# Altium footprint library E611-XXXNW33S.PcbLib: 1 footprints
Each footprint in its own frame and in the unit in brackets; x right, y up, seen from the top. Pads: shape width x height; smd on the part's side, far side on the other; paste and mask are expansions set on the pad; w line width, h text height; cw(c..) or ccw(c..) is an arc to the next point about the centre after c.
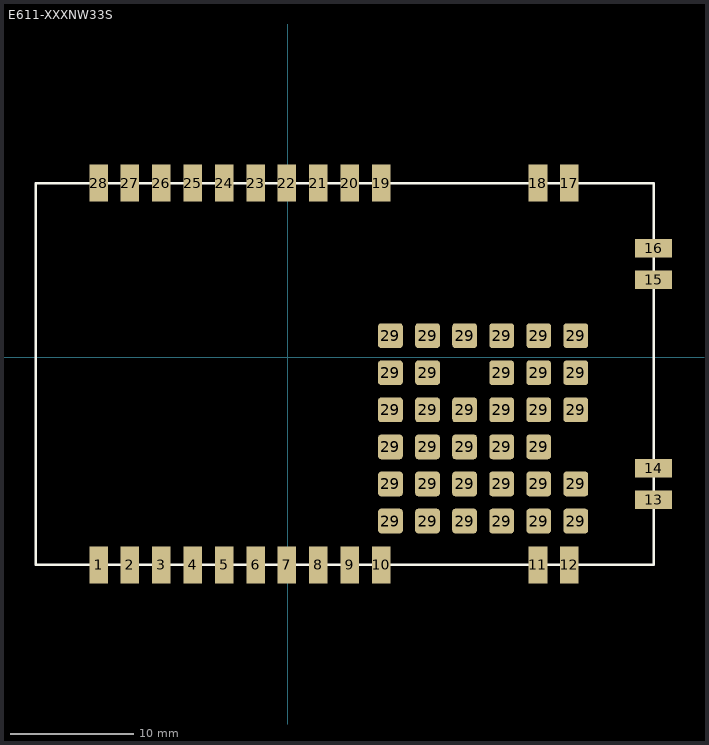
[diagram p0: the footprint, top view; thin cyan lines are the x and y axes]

## E611-XXXNW33S [mm]
pads (62):
  rect 1.5x3 smd: 1(-15.291,-16.815) 2(-12.751,-16.815) 3(-10.211,-16.815) 4(-7.671,-16.815) 5(-5.131,-16.815) 6(-2.591,-16.815) 7(-0.051,-16.815) 8(2.489,-16.815) 9(5.029,-16.815) 10(7.569,-16.815) 11(20.269,-16.815) 12(22.809,-16.815) 17(22.809,14.085) 18(20.269,14.085) 19(7.569,14.085) 20(5.029,14.085) 21(2.489,14.085) 22(-0.051,14.085) 23(-2.591,14.085) 24(-5.131,14.085) 25(-7.671,14.085) 26(-10.211,14.085) 27(-12.751,14.085) 28(-15.291,14.085)
  rect 3x1.5 smd: 13(29.629,-11.525) 14(29.629,-8.985) 15(29.629,6.255) 16(29.629,8.795)
  rrect25% 2x2 smd paste-2 mask-2: 29(8.329,-13.265) 29(8.329,-10.265) 29(8.329,-7.265) 29(8.329,-4.265) 29(8.329,-1.265) 29(8.329,1.735) 29(11.329,-13.265) 29(11.329,-10.265) 29(11.329,-7.265) 29(11.329,-4.265) 29(11.329,-1.265) 29(11.329,1.735) 29(14.329,-13.265) 29(14.329,-10.265) 29(14.329,-7.265) 29(14.329,-4.265) 29(14.329,1.735) 29(17.329,-13.265) 29(17.329,-10.265) 29(17.329,-7.265) 29(17.329,-4.265) 29(17.329,-1.265) 29(17.329,1.735) 29(20.329,-13.265) 29(20.329,-10.265) 29(20.329,-7.265) 29(20.329,-4.265) 29(20.329,-1.265) 29(20.329,1.735) 29(23.329,-13.265) 29(23.329,-10.265) 29(23.329,-4.265) 29(23.329,-1.265) 29(23.329,1.735)
Top Overlay:
  lines w0.203: -20.371,-16.815 29.629,-16.815 ; -20.371,-16.815 -20.371,14.085 ; -20.371,-16.815 29.629,-16.815 ; -20.371,-16.815 -20.371,14.085 ; -20.371,14.085 29.629,14.085 ; -20.371,14.085 29.629,14.085 ; 29.629,-16.815 29.629,14.085 ; 29.629,-16.815 29.629,14.085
